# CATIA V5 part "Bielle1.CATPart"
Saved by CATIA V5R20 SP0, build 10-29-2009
Part number: Bielle1
Bounding box of the stored display mesh (mm): x 11.975 to 41, y 23.501 to 42.999, z -8 to -5
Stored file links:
  E:\Boulot\SeaTech\2eme ANNEE\FabricationAdditive\TP_MOSM_CREM\Projet Sauterelle de serrage\CAO Assemblage Sauterelle\Bielle1.CATPart
  E:\Boulot\SeaTech\2eme ANNEE\FabricationAdditive\TP_MOSM_CREM\Projet Sauterelle de serrage\CAO Assemblage Sauterelle\Sauterelle_horizontale_05120-06.CATPart
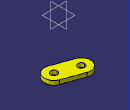
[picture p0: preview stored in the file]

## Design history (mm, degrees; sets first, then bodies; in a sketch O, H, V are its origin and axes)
Body1 (main body)
  Solid1 "05120-06_13": solid without history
